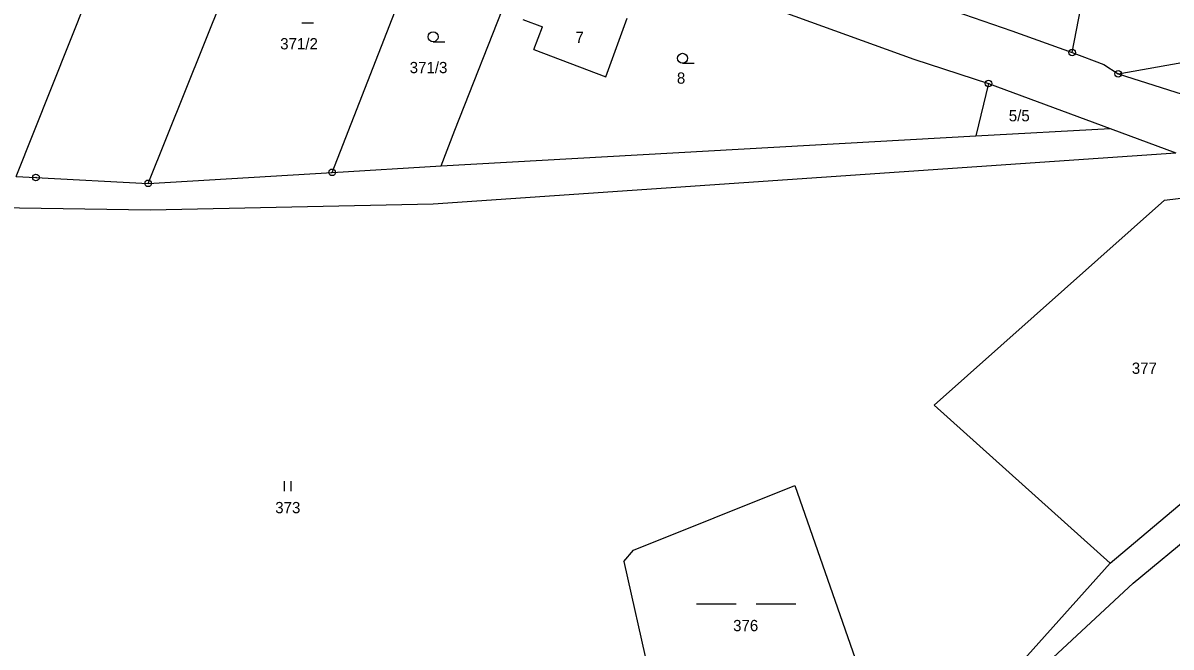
# Model space of a CAD drawing. Extents: x -633485 to -630509, y -1112692 to -1108818.
# Drawn here: x -632263.7 to -632090.4, y -1111932.7 to -1111838.6 of the extents above; entities that cross this region are included whole.
import ezdxf
from ezdxf.enums import TextEntityAlignment as Align

# ---------------------------------------------------------------- set-up
doc = ezdxf.new("R2010")
doc.units = 0
doc.header["$LTSCALE"] = 0.68
for name, color, linetype, lineweight in [('1', 7, 'Continuous', 25), ('3', 7, 'Continuous', 25), ('8', 7, 'Continuous', 25)]:
    doc.layers.add(name, color=color, linetype=linetype, lineweight=lineweight)
doc.layers.add('2', color=7, linetype='Continuous')

msp = doc.modelspace()

# ---------------------------------------------------------------- linework, layer by layer
at = {"layer": '1'}
for p, q in [((-632264.78, -1111861.71), (-632242.18, -1111805.12)), ((-632244.86, -1111862.76), (-632224.61, -1111812.39)), ((-632105.33, -1111843.03), (-632101.24, -1111821.96)), ((-632217.08, -1111861.1), (-632201.95, -1111822.48)), ((-632184.61, -1111823.98), (-632129.27, -1111844)), ((-632198.55, -1111854.72), (-632188.36, -1111828.9)), ((-632175.75, -1111846.71), (-632172.54, -1111837.85)), ((-632123.23, -1111836.74), (-632114.46, -1111839.74)), ((-632188.27, -1111838.03), (-632185.32, -1111839.15)), ((-632186.62, -1111842.58), (-632185.32, -1111839.15)), ((-632114.46, -1111839.74), (-632105.33, -1111843.03)), ((-632098.38, -1111846.22), (-632068.47, -1111840.91)), ((-632186.62, -1111842.58), (-632175.75, -1111846.71)), ((-632105.33, -1111843.03), (-632100.54, -1111844.84)), ((-632129.27, -1111844), (-632117.99, -1111847.69)), ((-632100.54, -1111844.84), (-632098.38, -1111846.22)), ((-632098.38, -1111846.22), (-632086.08, -1111850.17)), ((-632117.99, -1111847.69), (-632119.88, -1111855.61)), ((-632117.99, -1111847.69), (-632099.62, -1111854.48)), ((-632200.59, -1111860.11), (-632198.55, -1111854.72)), ((-632119.88, -1111855.61), (-632099.62, -1111854.48)), ((-632099.62, -1111854.48), (-632089.68, -1111858.15)), ((-632200.59, -1111860.11), (-632119.88, -1111855.61)), ((-632201.81, -1111865.84), (-632089.68, -1111858.15)), ((-632217.08, -1111861.1), (-632200.59, -1111860.11)), ((-632264.78, -1111861.71), (-632261.78, -1111861.87)), ((-632261.78, -1111861.87), (-632244.86, -1111862.76)), ((-632244.86, -1111862.76), (-632217.08, -1111861.1)), ((-632329.36, -1111865.46), (-632244.47, -1111866.78)), ((-632126.16, -1111896.22), (-632091.38, -1111865.28)), ((-632091.38, -1111865.28), (-632087.66, -1111864.83)), ((-632244.47, -1111866.78), (-632201.81, -1111865.84)), ((-632099.6, -1111920.09), (-632062.95, -1111889.09)), ((-632096.11, -1111923.1), (-632055.22, -1111889.02)), ((-632126.16, -1111896.22), (-632099.6, -1111920.09)), ((-632171.58, -1111918.09), (-632147.21, -1111908.33)), ((-632147.21, -1111908.33), (-632136.43, -1111939.2)), ((-632173.03, -1111919.8), (-632171.58, -1111918.09)), ((-632173.03, -1111919.8), (-632166.09, -1111950.56)), ((-632114.27, -1111936.4), (-632099.6, -1111920.09)), ((-632108.2, -1111934.31), (-632096.11, -1111923.1))]:
    msp.add_line(p, q, dxfattribs=at)
at = {"layer": '3'}
for p, q in [((-632221.623, -1111838.56), (-632219.873, -1111838.56)), ((-632201.823, -1111841.39), (-632200.073, -1111841.39)), ((-632164.163, -1111844.64), (-632162.413, -1111844.64)), ((-632224.271, -1111909.2), (-632224.271, -1111907.7)), ((-632223.27, -1111909.2), (-632223.27, -1111907.7)), ((-632162.059, -1111926.2), (-632156.059, -1111926.2)), ((-632153.059, -1111926.2), (-632147.059, -1111926.2))]:
    msp.add_line(p, q, dxfattribs=at)
for centre in [(-632201.8229, -1111840.6398), (-632164.1629, -1111843.8898)]:
    msp.add_circle(centre, 0.75, dxfattribs=at)
at = {"layer": '8'}
for centre, radius in [((-632105.33, -1111843.0299), 0.5), ((-632105.33, -1111843.0299), 0.0303), ((-632098.38, -1111846.2199), 0.5), ((-632098.38, -1111846.2199), 0.0303), ((-632117.99, -1111847.6899), 0.5), ((-632117.99, -1111847.6899), 0.0303), ((-632261.78, -1111861.8699), 0.5), ((-632261.78, -1111861.8699), 0.0303), ((-632217.08, -1111861.0999), 0.5), ((-632217.08, -1111861.0999), 0.0303), ((-632244.86, -1111862.7599), 0.5), ((-632244.86, -1111862.7599), 0.0303)]:
    msp.add_circle(centre, radius, dxfattribs=at)

# ---------------------------------------------------------------- texts
at = {"layer": '2'}
for s, p in [('371/2', (-632224.91, -1111842.545)), ('7', (-632180.34, -1111841.585)), ('371/3', (-632205.36, -1111846.135)), ('8', (-632165.02, -1111847.725)), ('377', (-632096.34, -1111891.505)), ('373', (-632225.66, -1111912.535)), ('376', (-632156.53, -1111930.335))]:
    msp.add_text(s, height=1.7, dxfattribs=at).set_placement(p)
msp.add_text('5/5', height=1.7, dxfattribs=at).set_placement((-632113.33, -1111853.402), align=Align.CENTER)

doc.saveas('drawing.dxf')
